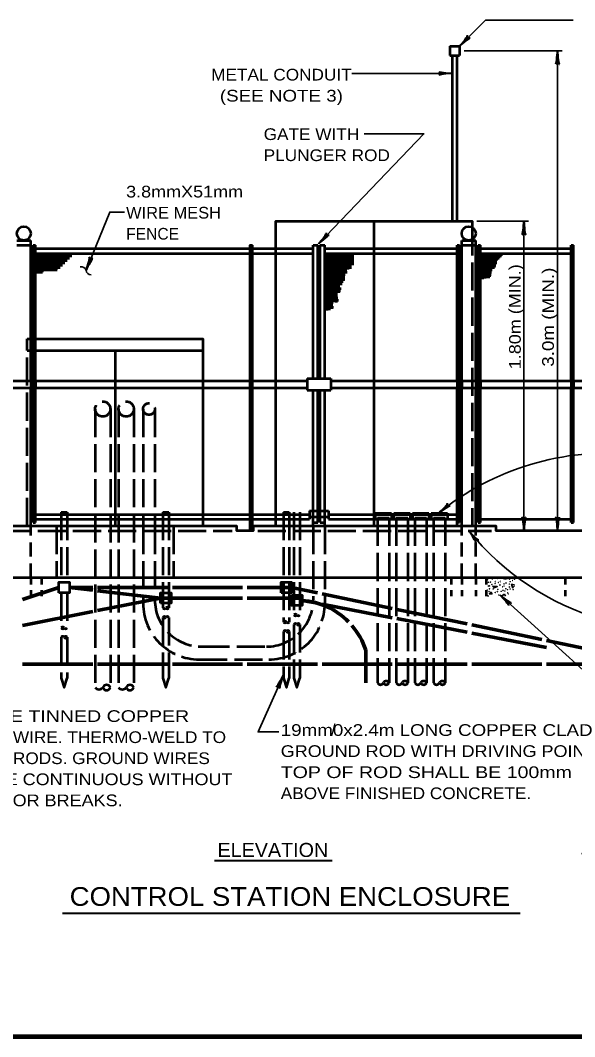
# Model space of a CAD drawing. Extents: x -30 to 826, y -11 to 533.
# Drawn here: x 172.3 to 314.5, y 0.9 to 261.5 of the extents above; entities that cross this region are included whole.
import ezdxf
from ezdxf.enums import TextEntityAlignment as Align

# ---------------------------------------------------------------- set-up
doc = ezdxf.new("R2010")
doc.units = 0
doc.header["$LTSCALE"] = 1.2
for name, pattern in [('LONG_DASHED', [7.5, 6, -1.5]), ('MEDIUM_DASHED', [4.5, 3, -1.5]), ('SHORT_DASHED', [2.7, 1.5, -1.2])]:
    doc.linetypes.add(name, pattern=pattern)
doc.layers.add('1', color=7, linetype='Continuous', lineweight=53)

msp = doc.modelspace()

# ---------------------------------------------------------------- linework, layer by layer
at = {"layer": '1'}
for p, q in [((282.536, 254.829), (284.936, 254.829)), ((282.536, 254.829), (282.536, 252.429)), ((284.936, 254.829), (284.936, 252.429)), ((282.536, 252.429), (284.936, 252.429)), ((283.136, 209.955), (283.136, 252.429)), ((284.336, 209.955), (284.336, 252.429)), ((263.036, 209.955), (263.036, 131.829)), ((171.419, 205.029), (175.019, 205.029)), ((171.419, 203.829), (175.019, 203.829)), ((175.019, 169.029), (175.019, 205.029)), ((175.619, 203.829), (176.219, 203.829)), ((175.619, 169.029), (175.619, 203.829)), ((176.219, 169.029), (176.219, 203.829)), ((231.836, 130.629), (231.836, 203.829)), ((247.436, 203.829), (248.636, 203.829)), ((247.436, 169.629), (247.436, 203.829)), ((248.636, 169.629), (248.636, 203.829)), ((249.236, 203.829), (250.436, 203.829)), ((249.236, 169.629), (249.236, 203.829)), ((250.436, 169.629), (250.436, 203.829)), ((284.336, 203.829), (284.936, 203.829)), ((284.336, 169.029), (284.336, 203.829)), ((284.936, 169.029), (284.936, 203.829)), ((285.536, 205.029), (289.136, 205.029)), ((285.536, 169.029), (285.536, 205.029)), ((285.536, 203.829), (289.136, 203.829)), ((289.136, 169.029), (289.136, 205.029)), ((289.736, 203.829), (290.336, 203.829)), ((289.736, 169.029), (289.736, 203.829)), ((290.336, 169.029), (290.336, 203.829)), ((313.619, 169.029), (313.619, 203.829)), ((313.619, 203.829), (314.219, 203.829)), ((314.219, 169.029), (314.219, 203.829)), ((176.219, 202.929), (231.236, 202.929)), ((176.219, 201.729), (231.236, 201.729)), ((176.219, 201.129), (185.519, 201.129)), ((176.819, 196.548), (176.819, 201.729)), ((177.419, 196.58), (177.419, 201.729)), ((178.019, 196.929), (178.019, 201.729)), ((178.619, 197.198), (178.619, 201.729)), ((179.219, 197.295), (179.219, 201.729)), ((179.819, 197.23), (179.819, 201.729)), ((180.419, 197.295), (180.419, 201.729)), ((181.019, 197.263), (181.019, 201.729)), ((181.619, 197.529), (181.619, 201.729)), ((182.219, 198.129), (182.219, 201.729)), ((182.819, 198.729), (182.819, 201.729)), ((183.419, 199.115), (183.419, 201.729)), ((184.019, 199.798), (184.019, 201.729)), ((184.619, 200.416), (184.619, 201.729)), ((185.219, 200.829), (185.219, 201.729)), ((231.836, 202.929), (247.436, 202.929)), ((231.836, 201.729), (247.436, 201.729)), ((250.436, 202.929), (284.336, 202.929)), ((250.436, 201.729), (284.336, 201.729)), ((250.436, 201.129), (257.903, 201.129)), ((251.036, 187.1), (251.036, 201.729)), ((251.636, 187.203), (251.636, 201.729)), ((252.236, 187.538), (252.236, 201.729)), ((252.836, 189.186), (252.836, 201.729)), ((253.436, 189.135), (253.436, 201.729)), ((254.036, 191.582), (254.036, 201.729)), ((254.636, 193.566), (254.636, 201.729)), ((255.236, 194.725), (255.236, 201.729)), ((255.836, 196.657), (255.836, 201.729)), ((256.436, 197.558), (256.436, 201.729)), ((257.036, 197.893), (257.036, 201.729)), ((257.636, 198.729), (257.636, 201.729)), ((290.336, 202.929), (313.619, 202.929)), ((290.336, 201.729), (313.619, 201.729)), ((290.354, 201.102), (295.754, 201.102)), ((290.954, 195.102), (290.954, 201.702)), ((291.554, 195.282), (291.554, 201.702)), ((292.154, 195.402), (292.154, 201.702)), ((292.754, 195.702), (292.754, 201.702)), ((293.354, 198.102), (293.354, 201.702)), ((293.954, 198.102), (293.954, 201.702)), ((294.554, 199.902), (294.554, 201.702)), ((295.154, 200.502), (295.154, 201.702)), ((295.754, 201.102), (295.754, 201.702)), ((176.219, 200.529), (184.919, 200.529)), ((176.219, 199.929), (184.319, 199.929)), ((176.219, 199.329), (183.719, 199.329)), ((176.219, 198.729), (183.119, 198.729)), ((176.219, 198.129), (182.519, 198.129)), ((250.436, 200.529), (257.903, 200.529)), ((250.436, 199.929), (257.8, 199.929)), ((250.436, 199.329), (257.775, 199.329)), ((250.436, 198.729), (257.208, 198.729)), ((250.436, 198.129), (257.26, 198.129)), ((290.354, 200.502), (295.154, 200.502)), ((290.354, 199.902), (294.554, 199.902)), ((290.354, 199.302), (294.554, 199.302)), ((290.354, 198.702), (294.254, 198.702)), ((290.354, 198.102), (293.954, 198.102)), ((176.219, 197.529), (181.77, 197.529)), ((176.219, 196.929), (178.019, 196.929)), ((250.436, 197.529), (256.101, 197.529)), ((250.436, 196.929), (256.127, 196.929)), ((250.436, 196.329), (255.663, 196.329)), ((250.436, 195.729), (255.56, 195.729)), ((290.354, 197.502), (293.354, 197.502)), ((290.354, 196.902), (293.174, 196.902)), ((290.354, 196.302), (293.054, 196.302)), ((290.354, 195.702), (292.754, 195.702)), ((250.436, 195.129), (255.534, 195.129)), ((250.436, 194.529), (255.148, 194.529)), ((250.436, 193.929), (254.865, 193.929)), ((250.436, 193.329), (254.298, 193.329)), ((250.436, 192.729), (254.659, 192.729)), ((250.436, 192.129), (254.427, 192.129)), ((250.436, 191.529), (253.654, 191.529)), ((250.436, 190.929), (253.68, 190.929)), ((250.436, 190.329), (253.783, 190.329)), ((250.436, 189.729), (253.938, 189.729)), ((250.436, 189.129), (252.547, 189.129)), ((250.436, 188.529), (252.496, 188.529)), ((250.436, 187.929), (252.624, 187.929)), ((174.119, 176.829), (219.119, 176.829)), ((196.619, 176.829), (196.619, 131.829)), ((245.936, 169.629), (245.936, 166.629)), ((245.936, 169.629), (251.936, 169.629)), ((251.936, 169.629), (251.936, 166.629)), ((142.619, 169.029), (245.936, 169.029)), ((142.619, 167.229), (245.936, 167.229)), ((175.019, 168.729), (175.019, 167.529)), ((175.019, 131.829), (175.019, 167.229)), ((175.619, 168.729), (175.619, 167.529)), ((175.619, 132.729), (175.619, 167.229)), ((176.219, 168.729), (176.219, 167.529)), ((176.219, 132.729), (176.219, 167.229)), ((251.936, 169.029), (318.419, 169.029)), ((251.936, 167.229), (318.419, 167.229)), ((284.336, 168.729), (284.336, 167.529)), ((284.336, 131.829), (284.336, 167.229)), ((284.936, 168.729), (284.936, 167.529)), ((284.936, 132.729), (284.936, 167.229)), ((285.536, 168.729), (285.536, 167.529)), ((285.536, 131.829), (285.536, 167.229)), ((289.136, 168.729), (289.136, 167.529)), ((289.136, 131.829), (289.136, 167.229)), ((289.736, 168.729), (289.736, 167.529)), ((289.736, 132.729), (289.736, 167.229)), ((290.336, 168.729), (290.336, 167.529)), ((290.336, 132.729), (290.336, 167.229)), ((313.619, 168.729), (313.619, 167.529)), ((313.619, 132.729), (313.619, 167.229)), ((314.219, 168.729), (314.219, 167.529)), ((314.219, 132.729), (314.219, 167.229)), ((245.936, 166.629), (251.936, 166.629)), ((247.436, 131.829), (247.436, 166.629)), ((248.636, 132.729), (248.636, 166.629)), ((249.236, 132.729), (249.236, 166.629)), ((250.436, 131.829), (250.436, 166.629)), ((246.536, 135.729), (246.536, 133.629)), ((246.536, 135.729), (248.336, 135.729)), ((249.536, 135.729), (251.336, 135.729)), ((251.336, 135.729), (251.336, 133.629)), ((176.219, 134.829), (246.536, 134.829)), ((176.219, 133.629), (246.536, 133.629)), ((182.819, 135.429), (184.319, 135.429)), ((208.919, 135.429), (210.419, 135.429)), ((208.919, 135.429), (210.419, 135.429)), ((239.819, 135.429), (241.319, 135.429)), ((246.536, 134.229), (251.336, 134.229)), ((251.336, 134.829), (284.936, 134.829)), ((251.336, 133.629), (284.336, 133.629)), ((263.336, 135.129), (263.336, 133.929)), ((267.536, 135.129), (267.536, 133.929)), ((268.136, 135.129), (268.136, 133.929)), ((272.336, 135.129), (272.336, 133.929)), ((272.936, 135.129), (272.936, 133.929)), ((277.136, 135.129), (277.136, 133.929)), ((277.736, 135.129), (277.736, 133.929)), ((281.936, 135.129), (281.936, 133.929)), ((290.336, 133.629), (313.619, 133.629)), ((175.619, 132.729), (176.219, 132.729)), ((247.436, 132.729), (248.636, 132.729)), ((249.236, 132.729), (250.436, 132.729)), ((284.936, 132.729), (284.336, 132.729)), ((289.736, 132.729), (290.336, 132.729)), ((313.619, 132.729), (314.219, 132.729)), ((140.219, 118.629), (192.119, 118.629)), ((192.119, 118.629), (211.319, 118.629)), ((211.319, 118.629), (230.519, 118.629)), ((230.519, 118.629), (291.836, 118.629)), ((291.836, 118.629), (320.819, 118.629))]:
    msp.add_line(p, q, dxfattribs=at)
at = {"layer": '1', "lineweight": 35}
for p, q in [((311.307, 253.629), (286.136, 253.629)), ((310.107, 253.629), (310.107, 130.629)), ((283.136, 247.856), (257.323, 247.856)), ((302.706, 209.955), (289.436, 209.955)), ((301.506, 209.955), (301.506, 130.629)), ((299.082, 116.513), (298.589, 115.985)), ((296.549, 114.329), (295.796, 113.918)), ((296.806, 113.878), (296.501, 114.353))]:
    msp.add_line(p, q, dxfattribs=at)
at = {"layer": '1', "linetype": 'LONG_DASHED'}
for p, q in [((288.236, 208.388), (288.236, 131.829)), ((174.119, 131.829), (174.119, 179.829)), ((191.519, 161.829), (191.519, 90.429)), ((195.419, 161.829), (195.419, 90.429)), ((197.519, 161.829), (197.519, 90.429)), ((201.419, 161.829), (201.419, 90.429)), ((182.819, 135.429), (182.819, 117.429)), ((184.319, 135.429), (184.319, 117.429)), ((208.919, 135.429), (208.919, 110.829)), ((210.419, 135.429), (210.419, 110.829)), ((239.819, 135.429), (239.819, 107.229)), ((241.319, 135.429), (241.319, 107.229)), ((242.519, 135.429), (242.519, 109.029)), ((244.019, 135.429), (244.019, 109.029)), ((263.336, 135.129), (267.536, 135.129)), ((263.936, 133.929), (266.936, 133.929)), ((263.936, 133.929), (263.936, 91.629)), ((266.936, 133.929), (266.936, 91.629)), ((268.136, 135.129), (272.336, 135.129)), ((268.736, 133.929), (271.736, 133.929)), ((268.736, 133.929), (268.736, 91.629)), ((271.736, 133.929), (271.736, 91.629)), ((272.936, 135.129), (277.136, 135.129)), ((273.536, 133.929), (276.536, 133.929)), ((273.536, 133.929), (273.536, 91.629)), ((276.536, 133.929), (276.536, 91.629)), ((277.736, 135.129), (281.936, 135.129)), ((278.336, 133.929), (281.336, 133.929)), ((278.336, 133.929), (278.336, 91.629)), ((281.336, 133.929), (281.336, 91.629)), ((167.819, 130.629), (226.619, 130.629)), ((181.619, 131.829), (181.619, 118.629)), ((211.619, 131.829), (211.619, 118.629)), ((233.219, 130.629), (293.219, 130.629)), ((247.436, 131.829), (247.436, 112.929)), ((250.436, 131.829), (250.436, 112.029)), ((182.819, 114.729), (182.819, 105.729)), ((184.319, 114.729), (184.319, 105.729)), ((208.919, 108.429), (208.919, 92.829)), ((210.419, 108.429), (210.419, 92.829)), ((239.819, 104.829), (239.819, 92.829)), ((241.319, 104.829), (241.319, 92.829)), ((242.519, 106.629), (242.519, 92.829)), ((244.019, 106.629), (244.019, 92.829)), ((182.819, 103.329), (182.819, 92.829)), ((184.319, 103.329), (184.319, 92.829)), ((218.819, 100.929), (235.436, 100.929)), ((218.219, 97.629), (236.036, 97.629))]:
    msp.add_line(p, q, dxfattribs=at)
at = {"layer": '1', "linetype": 'MEDIUM_DASHED'}
for p, q in [((175.019, 118.629), (175.019, 131.829)), ((285.536, 118.629), (285.536, 131.829)), ((289.136, 118.629), (289.136, 131.829))]:
    msp.add_line(p, q, dxfattribs=at)
at = {"layer": '1', "linetype": 'SHORT_DASHED'}
for p, q in [((175.019, 118.629), (175.019, 113.829)), ((177.719, 118.629), (177.719, 113.829)), ((282.836, 118.629), (282.836, 113.829)), ((285.536, 118.629), (285.536, 113.829)), ((289.136, 118.629), (289.136, 113.829)), ((291.836, 118.629), (291.836, 113.829)), ((299.036, 118.629), (301.386, 118.629)), ((312.119, 118.629), (312.119, 113.829))]:
    msp.add_line(p, q, dxfattribs=at)
at = {"layer": '1', "lineweight": 70}
for p, q in [((172.919, 112.971), (182.219, 116.079)), ((184.919, 116.079), (190.919, 116.079)), ((184.919, 116.079), (190.919, 115.387)), ((192.119, 116.079), (210.119, 116.079)), ((192.119, 115.248), (208.319, 113.379)), ((211.319, 116.079), (229.319, 116.079)), ((230.519, 116.079), (241.919, 116.079)), ((241.919, 116.079), (248.519, 114.707)), ((208.319, 113.379), (192.119, 110.145)), ((208.319, 113.379), (229.319, 113.379)), ((230.519, 113.379), (244.619, 113.379)), ((244.619, 112.779), (248.519, 112.027)), ((249.719, 114.457), (267.719, 110.715)), ((190.919, 109.905), (172.919, 106.312)), ((249.719, 111.796), (267.719, 108.325)), ((268.919, 110.465), (286.919, 106.722)), ((268.919, 108.094), (286.919, 104.623)), ((288.119, 106.473), (306.119, 102.73)), ((288.119, 104.392), (307.319, 100.69)), ((307.319, 102.48), (324.964, 98.811)), ((260.936, 100.029), (260.936, 91.629)), ((172.919, 96.429), (190.919, 96.429)), ((192.119, 96.429), (210.119, 96.429)), ((211.319, 96.429), (229.319, 96.429)), ((230.519, 96.429), (248.519, 96.429)), ((249.719, 96.429), (267.719, 96.429)), ((268.919, 96.429), (286.919, 96.429)), ((288.119, 96.429), (306.119, 96.429)), ((307.319, 96.429), (325.319, 96.429))]:
    msp.add_line(p, q, dxfattribs=at)
at = {"layer": '1', "lineweight": 40}
for p, q in [((222.091, 46.14), (252.318, 46.14)), ((183.136, 32.596), (300.504, 32.596))]:
    msp.add_line(p, q, dxfattribs=at)
at = {"layer": '1', "lineweight": 158}
msp.add_line((819.196, 0.944), (27.596, 0.944), dxfattribs=at)
at = {"layer": '1', "lineweight": 35}
for points in [[(284.936, 254.829), (291.655, 261.456), (314.107, 261.456)], [(248.808, 204.172), (275.862, 232.333), (260.485, 232.333)], [(189.188, 197.406), (195.246, 212.307), (199.003, 212.307)], [(296.074, 118.629), (295.757, 118.457), (296.933, 118.241), (296.683, 118.629)], [(293.069, 114.953), (292.613, 114.473), (293.309, 114.425), (293.069, 114.904)], [(298.613, 115.937), (298.325, 116.897), (299.116, 116.734)], [(295.374, 114.118), (331.752, 81.326), (316.441, 47.711), (320.757, 47.711)], [(239.819, 93.583), (233.291, 79.072), (238.673, 79.072)]]:
    msp.add_lwpolyline(points, dxfattribs=at)
at = {"layer": '1'}
for points in [[(237.836, 131.829), (237.836, 209.955), (288.236, 209.955), (288.236, 208.388)], [(231.236, 130.629), (231.236, 203.829), (231.836, 203.829)], [(174.119, 179.829), (219.119, 179.829), (219.119, 131.829)], [(320.819, 130.629), (294.419, 130.629), (294.419, 131.829), (232.019, 131.829), (232.019, 130.629), (227.819, 130.629), (227.819, 131.829), (166.619, 131.829), (166.619, 130.629)], [(182.819, 92.829), (183.569, 90.429), (184.319, 92.829)], [(208.919, 92.829), (209.669, 90.429), (210.419, 92.829)], [(239.819, 92.829), (240.569, 90.429), (241.319, 92.829)], [(242.519, 92.829), (243.269, 90.429), (244.019, 92.829)]]:
    msp.add_lwpolyline(points, dxfattribs=at)
at = {"layer": '1', "linetype": 'LONG_DASHED'}
for points in [[(203.819, 161.829), (203.819, 131.829), (203.819, 112.029)], [(206.819, 161.829), (206.819, 131.829), (206.819, 112.929)]]:
    msp.add_lwpolyline(points, dxfattribs=at)
at = {"layer": '1'}
for points in [[(182.219, 114.729), (182.219, 117.429), (184.919, 117.429), (184.919, 114.729)], [(239.219, 114.729), (239.219, 117.429), (241.919, 117.429), (241.919, 114.729)], [(208.319, 112.029), (208.319, 114.729), (211.019, 114.729), (211.019, 112.029)], [(241.919, 114.129), (244.619, 114.129), (244.619, 111.429), (241.919, 111.429)]]:
    msp.add_lwpolyline(points, close=True, dxfattribs=at)
at = {"layer": '1', "lineweight": 35}
msp.add_lwpolyline([(293.405, 116.441), (294.653, 116.297), (293.837, 116.009)], close=True, dxfattribs=at)
at = {"layer": '1'}
for centre in [(173.219, 206.829), (287.336, 206.829)]:
    msp.add_circle(centre, 1.8, dxfattribs=at)
at = {"layer": '1', "linetype": 'LONG_DASHED'}
for centre, radius in [((193.469, 161.829), 1.95), ((199.469, 161.829), 1.95), ((205.319, 161.829), 1.5)]:
    msp.add_circle(centre, radius, dxfattribs=at)
at = {"layer": '1', "lineweight": 35}
for centre in [(292.197, 118.515), (292.212, 118.133), (292.403, 117.418), (292.476, 118.42), (292.905, 117.481), (293.414, 118.213), (294.178, 117.608), (294.273, 118.483), (294.687, 118.436), (295.005, 117.354), (295.482, 117.608), (296.881, 117.211), (297.358, 118.372), (297.82, 118.261), (297.963, 117.577), (298.615, 117.863), (299.06, 118.197), (292.101, 115.413), (292.38, 116.444), (292.54, 115.037), (292.651, 116.463), (292.651, 115.747), (293.303, 116.861), (293.621, 115.699), (294.114, 117.131), (294.146, 114.783), (294.687, 114.989), (294.814, 115.604), (295.339, 116.733), (295.657, 115.101), (296.054, 116.24), (296.134, 115.334), (296.388, 117.004), (296.436, 116.415), (296.611, 115.18), (296.85, 115.763), (297.279, 115.524), (297.358, 114.703), (297.756, 116.208), (297.804, 116.924), (297.979, 115.699), (298.758, 115.524), (292.197, 113.955), (295.068, 114.162), (297.549, 114.448)]:
    msp.add_circle(centre, 0.0318, dxfattribs=at)
for centre, radius, start, end in [((187.945, 197.002), 1.307, 17.97301, 102.52429), ((190.488, 197.54), 1.307, 185.89086, 270.44213), ((322.958, 81.674), 68.847, 84.36386, 129.06474), ((340.984, 174.124), 69.056, 219.03891, 253.64268), ((292.476, 113.86), 0.0318, 31.47411, 156.62401)]:
    msp.add_arc(centre, radius, start, end, dxfattribs=at)
at = {"layer": '1', "linetype": 'LONG_DASHED'}
for centre, radius, start, end in [((218.219, 112.029), 14.4, 180, 270), ((218.819, 112.929), 12, 180, 270), ((235.436, 112.929), 12, 270, 0), ((236.036, 112.029), 14.4, 270, 0)]:
    msp.add_arc(centre, radius, start, end, dxfattribs=at)
at = {"layer": '1', "lineweight": 70}
for start, end in [(44.63463, 85.66375), (18.32925, 40.57602)]:
    msp.add_arc((243.207, 94.156), 18.677, start, end, dxfattribs=at)
at = {"layer": '1'}
for centre, radius, start, end in [((209.294, 111.045), 0.433, 209.9406, 330.0594), ((210.044, 110.613), 0.433, 29.9406, 150.0594), ((210.044, 111.045), 0.433, 209.9406, 330.0594), ((209.294, 108.213), 0.433, 29.9406, 150.0594), ((209.294, 108.645), 0.433, 209.9406, 330.0594), ((210.044, 108.213), 0.433, 29.9406, 150.0594), ((240.194, 107.013), 0.433, 29.9406, 150.0594), ((240.194, 107.445), 0.433, 209.9406, 330.0594), ((240.944, 107.445), 0.433, 209.9406, 330.0594), ((242.894, 108.813), 0.433, 29.9406, 150.0594), ((242.894, 109.245), 0.433, 209.9406, 330.0594), ((242.894, 106.413), 0.433, 29.9406, 150.0594), ((243.644, 109.245), 0.433, 209.9406, 330.0594), ((243.644, 106.413), 0.433, 29.9406, 150.0594), ((183.194, 105.513), 0.433, 29.9406, 150.0594), ((183.194, 105.945), 0.433, 209.9406, 330.0594), ((183.944, 105.945), 0.433, 209.9406, 330.0594), ((240.194, 104.613), 0.433, 29.9406, 150.0594), ((240.944, 104.613), 0.433, 29.9406, 150.0594), ((240.944, 105.045), 0.433, 209.9406, 330.0594), ((243.644, 106.845), 0.433, 209.9406, 330.0594), ((183.194, 103.113), 0.433, 29.9406, 150.0594), ((183.944, 103.113), 0.433, 29.9406, 150.0594), ((183.944, 103.545), 0.433, 209.9406, 330.0594), ((264.686, 92.013), 0.843, 207.12599, 332.87401), ((266.186, 91.245), 0.843, 27.12599, 152.87401), ((266.186, 92.013), 0.843, 207.12599, 332.87401), ((269.486, 92.013), 0.843, 207.12599, 332.87401), ((270.986, 91.245), 0.843, 27.12599, 152.87401), ((270.986, 92.013), 0.843, 207.12599, 332.87401), ((274.286, 92.013), 0.843, 207.12599, 332.87401), ((275.786, 91.245), 0.843, 27.12599, 152.87401), ((275.786, 92.013), 0.843, 207.12599, 332.87401), ((279.086, 92.013), 0.843, 207.12599, 332.87401), ((280.586, 91.245), 0.843, 27.12599, 152.87401), ((280.586, 92.013), 0.843, 207.12599, 332.87401), ((192.494, 91.237), 1.266, 219.64775, 320.35225), ((194.444, 90.076), 1.037, 19.89805, 160.10195), ((194.444, 90.782), 1.037, 199.89805, 340.10195), ((198.494, 91.174), 1.227, 217.36444, 322.63556), ((200.444, 90.076), 1.037, 19.89805, 160.10195), ((200.444, 90.782), 1.037, 199.89805, 340.10195)]:
    msp.add_arc(centre, radius, start, end, dxfattribs=at)
at = {"layer": '1', "lineweight": 40}
for centre, major_axis, ratio, start_param, end_param in [((285.636, 255.985), (-1.394, -1.638), 0.122415, 0.8963533, 3.1415927), ((285.636, 255.985), (-1.394, -1.638), 0.122415, 0.8963533, 3.1415927), ((286.072, 255.593), (1.649, 1.33), 0.07063, 6.2823074, 8.5597026), ((286.072, 255.593), (1.649, 1.33), 0.07063, 6.2823074, 8.5597026), ((309.853, 252.285), (0.211, 2.108), 0.07063, 3.1407148, 5.41811), ((309.853, 252.285), (0.211, 2.108), 0.07063, 3.1407148, 5.41811), ((310.438, 252.32), (-0.187, 2.143), 0.122415, 0.8963533, 3.1415927), ((310.438, 252.32), (-0.187, 2.143), 0.122415, 0.8963533, 3.1415927), ((281.827, 247.524), (2.143, 0.187), 0.122415, 0.8963533, 3.1415927), ((281.827, 247.524), (2.143, 0.187), 0.122415, 0.8963533, 3.1415927), ((281.792, 248.11), (2.108, -0.211), 0.07063, 3.1407148, 5.41811), ((281.792, 248.11), (2.108, -0.211), 0.07063, 3.1407148, 5.41811), ((301.252, 208.61), (0.211, 2.108), 0.07063, 3.1407148, 5.41811), ((301.252, 208.61), (0.211, 2.108), 0.07063, 3.1407148, 5.41811), ((301.838, 208.645), (-0.187, 2.143), 0.122415, 0.8963533, 3.1415927), ((301.838, 208.645), (-0.187, 2.143), 0.122415, 0.8963533, 3.1415927), ((249.476, 205.345), (-1.349, -1.675), 0.122415, 0.8963533, 3.1415927), ((249.476, 205.345), (-1.349, -1.675), 0.122415, 0.8963533, 3.1415927), ((249.923, 204.965), (-1.612, -1.374), 0.07063, 3.1407148, 5.41811), ((249.923, 204.965), (-1.612, -1.374), 0.07063, 3.1407148, 5.41811), ((189.374, 198.744), (-0.633, -2.056), 0.122415, 0.8963533, 3.1415927), ((189.93, 198.556), (0.989, 1.873), 0.07063, 6.2823074, 8.5597026), ((280.379, 136.212), (-1.546, -1.496), 0.122415, 0.8963533, 3.1415927), ((280.775, 135.779), (-1.769, -1.165), 0.07063, 3.1407148, 5.41811), ((301.174, 131.939), (0.187, -2.143), 0.122415, 0.8963533, 3.1415927), ((301.76, 131.974), (-0.211, -2.108), 0.07063, 3.1407148, 5.41811), ((309.775, 131.939), (0.187, -2.143), 0.122415, 0.8963533, 3.1415927), ((309.775, 131.939), (0.187, -2.143), 0.122415, 0.8963533, 3.1415927), ((310.361, 131.974), (-0.211, -2.108), 0.07063, 3.1407148, 5.41811), ((310.361, 131.974), (-0.211, -2.108), 0.07063, 3.1407148, 5.41811), ((287.997, 129.425), (1.164, -1.77), 0.07063, 6.2823074, 8.5597026), ((287.997, 129.425), (1.164, -1.77), 0.07063, 6.2823074, 8.5597026), ((288.43, 129.821), (-1.495, 1.546), 0.122415, 0.8963533, 3.1415927), ((288.43, 129.821), (-1.495, 1.546), 0.122415, 0.8963533, 3.1415927), ((296.203, 113.029), (1.424, -1.568), 0.07063, 6.2823074, 8.5597026), ((296.203, 113.029), (1.424, -1.568), 0.07063, 6.2823074, 8.5597026), ((296.569, 113.487), (-1.717, 1.296), 0.122415, 0.8963533, 3.1415927), ((296.569, 113.487), (-1.717, 1.296), 0.122415, 0.8963533, 3.1415927), ((239.036, 92.461), (-1.057, -1.836), 0.07063, 6.2823074, 8.5597026), ((239.584, 92.253), (0.708, 2.031), 0.122415, 0.8963533, 3.1415927)]:
    msp.add_ellipse(centre, major_axis=major_axis, ratio=ratio, start_param=start_param, end_param=end_param, dxfattribs=at)

# ---------------------------------------------------------------- texts
at = {"layer": '1'}
for s, height, width, p in [('METAL CONDUIT', 3, 1.1, (239.289, 246.032)), ('(SEE NOTE 3)', 3, 1.2, (239.289, 240.632)), ('CONTROL STATION ENCLOSURE', 4.8, 1.1, (241.47, 34.48))]:
    msp.add_text(s, height=height, dxfattribs=dict(at, width=width)).set_placement(p, align=Align.CENTER)
for s, height, width, p in [('GATE WITH', 3, 1.1, (234.746, 230.776)), ('PLUNGER ROD', 3, 1.1, (234.746, 225.376)), ('3.8mmX51mm', 3, 1.15, (199.456, 216.044)), ('WIRE MESH', 3, 1.05, (199.456, 210.644)), (' 4/0 BARE TINNED COPPER', 3, 1.25, (149.589, 81.613)), ('19mm0x2.4m LONG COPPER CLAD', 3, 1.2, (239.117, 78.035)), ('GROUND WIRE. THERMO-WELD TO', 3, 1.1, (149.589, 76.213)), ('GROUND ROD WITH DRIVING POINT.', 3, 1.15, (239.117, 72.635)), ('GROUND RODS. GROUND WIRES', 3, 1.1, (149.589, 70.813)), ('SHALL BE CONTINUOUS WITHOUT', 3, 1.15, (149.589, 65.413)), ('TOP OF ROD SHALL BE 100mm', 3, 1.25, (239.117, 67.235)), ('SPLICES OR BREAKS.', 3, 1.15, (149.589, 60.013)), ('ABOVE FINISHED CONCRETE.', 3, 1.1, (239.117, 61.835)), ('ELEVATION', 3.6, 1.05, (222.911, 47.007))]:
    msp.add_text(s, height=height, dxfattribs=dict(at, width=width)).set_placement(p)
msp.add_text('FENCE', height=3, dxfattribs=at).set_placement((199.456, 205.244))
for s, width, p in [('1.80m (MIN.)', 1.15, (300.692, 185.475)), ('3.0m (MIN.)', 1.2, (309.185, 185.37))]:
    msp.add_text(s, height=3, rotation=90, dxfattribs=dict(at, width=width)).set_placement(p, align=Align.CENTER)
msp.add_text('/', height=3, dxfattribs=at).set_placement((252.601, 78.069), align=Align.CENTER)

doc.saveas('drawing.dxf')
